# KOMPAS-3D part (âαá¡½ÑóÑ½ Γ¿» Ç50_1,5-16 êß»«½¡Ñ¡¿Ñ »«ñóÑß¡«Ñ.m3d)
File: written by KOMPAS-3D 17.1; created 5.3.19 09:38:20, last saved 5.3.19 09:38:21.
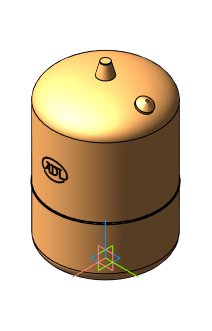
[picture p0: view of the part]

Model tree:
1. Операция без истории:1  (labels: Сталь 20  ГОСТ 1050-2013)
